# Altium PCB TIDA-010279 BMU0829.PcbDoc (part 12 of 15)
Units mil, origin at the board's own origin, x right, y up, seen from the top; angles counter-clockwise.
Board outline 11269.69 x 4438.98 mil, 4 copper layers (Top Layer, Signal Layer 1, Signal Layer 2, Bottom Layer), stack 61.6 mil thick; 1494 components, 725 nets, 3766 pads, 2728 vias.
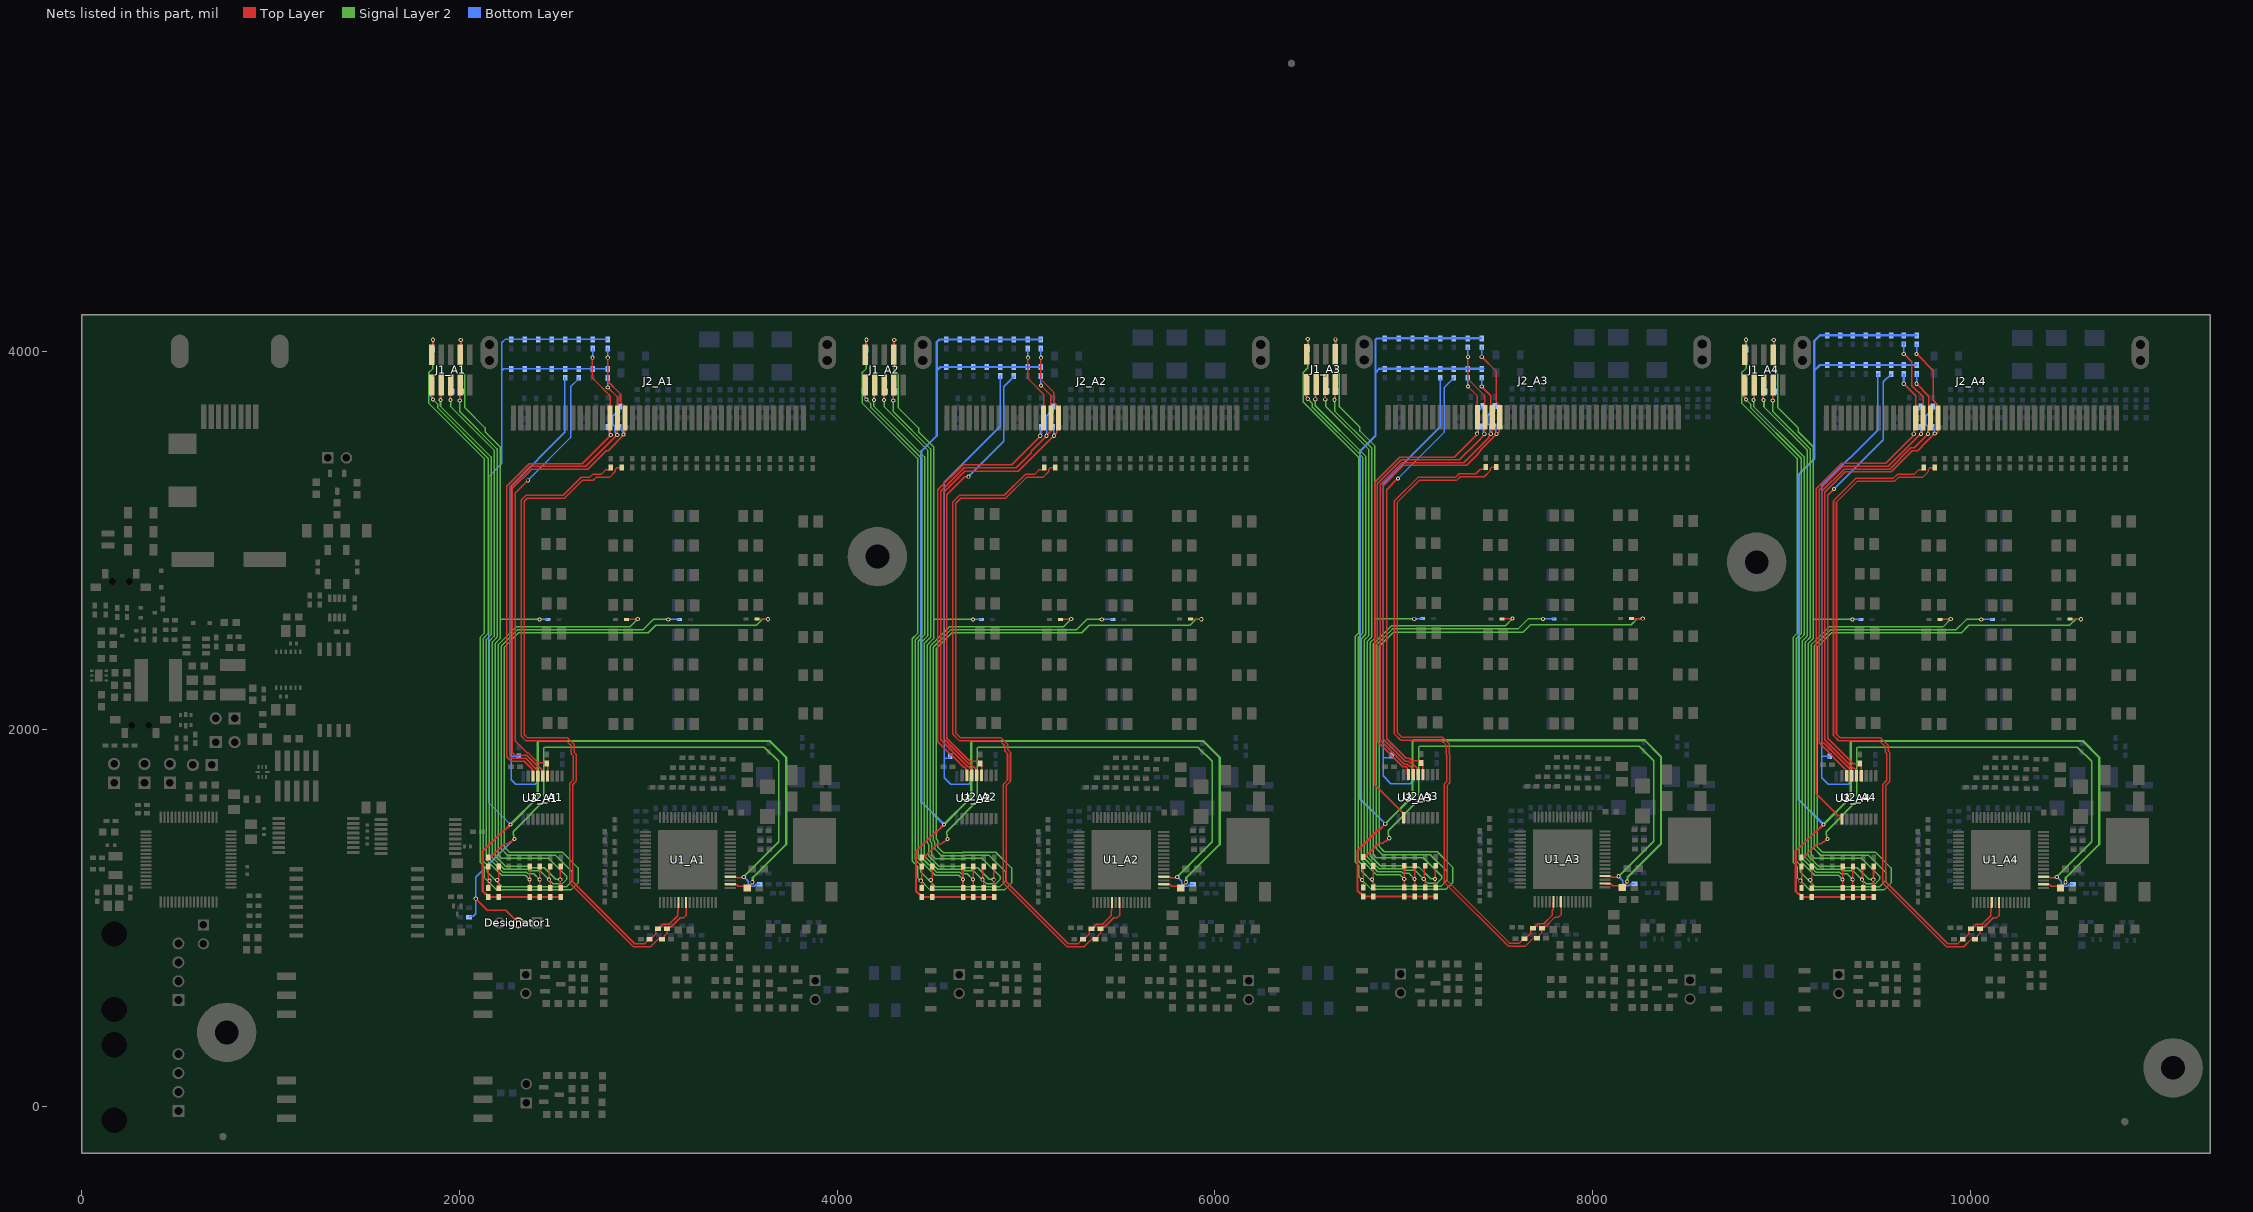
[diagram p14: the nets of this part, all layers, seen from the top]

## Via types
v1: diameter 22.01, hole 12.01, Top Layer to Bottom Layer, tented both sides, 2578 vias
v2: diameter 19.68, hole 7.87, Top Layer to Bottom Layer, tented both sides, 144 vias
v3: diameter 92.52, hole 49.21, Top Layer to Bottom Layer, 4 vias
v4: diameter 19.68, hole 7.87, Top Layer to Bottom Layer, 2 vias

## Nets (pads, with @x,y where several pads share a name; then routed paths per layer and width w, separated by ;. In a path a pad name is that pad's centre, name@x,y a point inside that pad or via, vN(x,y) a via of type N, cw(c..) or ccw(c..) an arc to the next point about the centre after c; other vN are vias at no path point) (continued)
TS11_A3: C122_A3.1 J2_A3.27 R218_A3.1 U2_A3.1 | length 2916.5
  Top Layer w7: U2_A3.1@6998.99,1531 6998.99,1551.67 6845.14,1705.52 6845.14,3296.04 6845.14,3305.88 6979.55,3440.29 7267.9,3440.29 v1@7391.73,3564.12 ; J2_A3.27@7389.59,3650.33 7391.73,3648.19 v1@7391.73,3562.99
  Top Layer w8: v1(7339.1,3813.3) 7389.59,3762.8 7389.59,3702.93 J2_A3.27@7391.73,3700.79
  Bottom Layer w7: v1@7391.73,3564.12 7392.74,3565.13 7392.74,3681.57 7417.43,3706.26 C122_A3.1@7417.43,3710.2
  Bottom Layer w8: R218_A3.1@7338.3,3860.24 7338.3,3819.77 7339.17,3818.9 v1@7342.52,3818.9
  other v1: 7388,3564.12
TS11_A4: C122_A4.1 J2_A4.27 R218_A4.1 U2_A4.1 | length 2896.6
  Top Layer w7: U2_A4.1@9320.14,1524.55 9320.14,1534.91 9314.78,1540.27 9300.53,1540.27 9184.01,1656.79 9184.01,3272.39 9318.34,3406.72 9551.65,3406.72 9697.05,3552.12 9697.05,3560.12 v1(9699.92,3562.99) ; v1(9647.07,3828.74) 9709.82,3765.99 J2_A4.27@9709.82,3705.89 ; v1@9704.72,3571.63 9704.72,3642.02 J2_A4.27@9709.82,3647.12
  Top Layer w12: J2_A4.27@9704.72,3700.79 J2_A4.27@9709.82,3705.89
  Bottom Layer w7: v1(9699.92,3562.99) 9699.92,3653.37 9714.57,3668.02 9714.57,3679.96 9737.66,3703.05 C122_A4.1@9737.66,3706.99
  Bottom Layer w12: R218_A4.1@9645.67,3877.95 9647.07,3876.55 v1(9647.07,3828.74)
TS12_A1: C117_A1.1 J2_A1.7 R217_A1.1 U2_A1.15 | length 2795.7
  Top Layer w7: 2384.68,1788.55 2342.52,1830.71 2273.62,1830.71 2250.37,1853.96 2250.37,3286.22 2369.88,3405.73 2648.8,3405.73 2797.35,3554.29 J2_A1.7@2797.35,3647.12
  Top Layer w8: 2384.68,1788.55 2384.68,1757.35 U2_A1.15@2389.54,1752.49 ; v1(2703.88,3966.54) 2703.88,3858.25 2797.35,3764.78 2797.35,3693.02 J2_A1.7@2795.28,3690.94
  Bottom Layer w7: C117_A1.1@2784.32,3598.72 2792.63,3590.41 2792.63,3569.92 2800.6,3561.94 v1@2800.6,3557.88
  Bottom Layer w8: v1@2706.69,3966.54 2705.29,3967.94 2705.29,4014.34 R217_A1.1@2706.69,4015.75
  other v1: 2800.6,3557.53
TS12_A2: C117_A2.1 J2_A2.7 R217_A2.1 U2_A2.15 | length 2733.2
  Top Layer w7: U2_A2.15@4687.14,1755.85 4681.78,1761.2 4681.78,1788.94 4673.98,1796.75 4669.79,1796.75 4533.53,1933 4533.53,3266.23 4667.02,3399.72 4923.56,3399.72 5075,3551.16 5075,3557.21 5084.02,3566.23 5084.02,3638.77 J2_A2.7@5092.37,3647.12
  Top Layer w8: v1(5009.84,3966.54) 5009.84,3855.44 5092.37,3772.92 5092.37,3704.57 J2_A2.7@5088.58,3700.79
  Bottom Layer w7: v1(5075,3553.15) 5075,3594.39 C117_A2.1@5079.33,3598.72
  Bottom Layer w8: v1(5009.84,3966.54) R217_A2.1@5009.84,4011.81
TS12_A3: C117_A3.1 J2_A3.7 R217_A3.1 U2_A3.15 | length 2780.6
  Top Layer w7: U2_A3.15@7024.58,1759.35 7019.23,1764.71 7019.23,1792.45 7011.42,1800.25 6994.91,1800.25 6860.02,1935.15 6860.02,3289.88 6860.02,3299.72 6985.71,3425.42 7293.53,3425.42 7387.8,3519.69 v1@7428.96,3560.85 ; v1@7429.4,3562.99 J2_A3.7@7429.4,3649.89
  Top Layer w8: v1(7339.1,3970.78) 7339.1,3854.06 7428.96,3764.19 7428.96,3702.93 J2_A3.7@7431.1,3700.79
  Bottom Layer w7: C117_A3.1@7415.93,3601.93 7421.61,3596.24 v1@7421.61,3562.99
  Bottom Layer w8: R217_A3.1@7338.3,4021.65 7338.3,3977.25 7339.17,3976.38 v1@7342.52,3976.38
  other v1: 7426.12,3562.99
TS12_A4: C117_A4.1 J2_A4.7 R217_A4.1 U2_A4.15 | length 2759.5
  Top Layer w7: U2_A4.15@9345.73,1752.89 9340.37,1758.25 9340.37,1785.99 9198.89,1927.47 9198.89,3266.23 9324.5,3391.85 9565.27,3391.85 9737.02,3563.59 9747.45,3574.03 9747.45,3645.38 J2_A4.7@9749.19,3647.12 ; v1(9647.07,3986.22) 9689.69,3943.61 9689.69,3818.44 9749.19,3758.93 J2_A4.7@9749.19,3695.69
  Top Layer w12: J2_A4.7@9749.19,3695.69 J2_A4.7@9753.94,3690.94
  Bottom Layer w7: v1(9647.07,3986.22) R217_A4.1@9647.07,4037.4 ; C117_A4.1@9736.16,3598.72 9737.61,3597.27 v1(9737.61,3562.99)
  Bottom Layer w12: R217_A4.1@9645.67,4045.28 9647.07,4043.87 R217_A4.1@9647.07,4037.4
TS13_A1: C112_A1.1 J2_A1.28 R216_A1.1 U2_A1.14 | length 2767.2
  Top Layer w7: U2_A1.14@2415.13,1752.49 2409.77,1757.85 2409.77,1785.59 2349.78,1845.58 2279.78,1845.58 2265.25,1860.12 2265.25,3280.06 2376.04,3390.86 2669,3390.86 v1(2835.68,3557.53) ; v1@2836.2,3558.06 2835.68,3558.58 2835.68,3646.08 J2_A1.28@2836.72,3647.12
  Top Layer w8: v1(2785.43,3809.06) 2836.72,3757.77 2836.72,3702.86 J2_A1.28@2834.65,3700.79
  Bottom Layer w7: v1@2835.68,3557.88 2835.68,3561.19 2822.13,3574.74 2822.13,3604.3 2811.73,3614.69 2811.73,3656.65 2829.67,3674.59 2842.65,3674.59 2848.51,3680.44 C112_A1.1@2848.51,3706.99
  Bottom Layer w8: v1(2785.43,3809.06) R216_A1.1@2785.43,3858.27
TS13_A2: C112_A2.1 J2_A2.28 R216_A2.1 U2_A2.14 | length 2730.4
  Top Layer w7: U2_A2.14@4712.73,1755.85 4707.37,1761.2 4707.37,1788.94 4696.36,1799.95 4691.81,1799.95 4680.14,1811.62 4679.62,1811.62 4548.41,1942.84 4548.41,3260.07 4673.18,3384.85 4948.12,3384.85 5026.76,3463.48 5026.76,3471.64 v1(5108.27,3553.15) ; v1@5108.27,3554.66 5129.37,3575.76 5129.37,3644.76 J2_A2.28@5131.74,3647.12
  Top Layer w8: v1(5078.74,3818.9) 5131.74,3765.9 5131.74,3704.57 J2_A2.28@5127.95,3700.79
  Bottom Layer w7: v1(5108.27,3553.15) 5108.27,3658.17 5124.68,3674.59 5137.67,3674.59 5143.53,3680.44 C112_A2.1@5143.53,3706.99
  Bottom Layer w8: v1(5078.74,3818.9) R216_A2.1@5078.74,3868.11
TS13_A3: C112_A3.1 J2_A3.28 R216_A3.1 U2_A3.14 | length 2762.2
  Top Layer w7: U2_A3.14@7049.28,1763.85 7044.82,1768.31 7044.82,1792.45 7034.1,1803.16 7029.54,1803.16 7017.58,1815.12 7001.07,1815.12 6874.89,1941.31 6874.89,3237.52 6874.89,3244.35 6874.89,3283.72 6874.89,3293.56 6991.87,3410.54 7317.09,3410.54 7449.21,3542.66 7449.21,3547.87 7460.28,3558.93 v1(7460.28,3562.99) ; v1(7412.21,3813.3) 7459.98,3765.53 7459.98,3711.28 J2_A3.28@7470.47,3700.79 ; v1@7464.11,3563.13 7466.98,3566 7466.98,3573.4 7468.33,3574.76 J2_A3.28@7468.33,3650.33
  Bottom Layer w7: v1@7411.42,3818.9 7412.21,3819.69 7412.21,3859.44 R216_A3.1@7411.42,3860.24 ; v1(7460.28,3562.99) 7461.24,3563.95 7461.24,3575.47 7453.74,3582.97 7453.74,3607.5 7443.34,3617.9 7443.34,3659.86 7461.28,3677.79 7474.27,3677.79 7480.13,3683.65 C112_A3.1@7480.13,3710.2
TS13_A4: C112_A4.1 J2_A4.28 R216_A4.1 U2_A4.14 | length 2729.6
  Top Layer w7: U2_A4.14@9370.08,1761.81 9365.96,1765.93 9365.96,1785.99 9226.16,1925.79 9221.61,1925.79 9213.76,1933.63 9213.76,3260.07 9330.66,3376.97 9571.44,3376.97 9683.75,3489.28 9701.59,3489.28 v1(9775.3,3562.99) 9775.3,3567.05 9779.91,3571.66 9779.91,3638.47 J2_A4.28@9788.56,3647.12 ; v1(9714.57,3828.74) 9780.21,3763.09 9780.21,3704.04 J2_A4.28@9783.46,3700.79
  Bottom Layer w7: v1(9714.57,3828.74) R216_A4.1@9714.57,3879.92 R216_A4.1@9714.57,3887.79 ; v1(9775.3,3562.99) 9773.97,3564.33 9773.97,3604.3 9763.57,3614.69 9763.57,3656.65 9781.51,3674.59 9794.5,3674.59 9800.36,3680.44 C112_A4.1@9800.36,3706.99
TS14_A1: C109_A1.1 J2_A1.8 R224_A1.1 U2_A1.13 | length 2823.4
  Top Layer w7: U2_A1.13@2440.72,1752.49 2440.72,1773.16 2435.36,1778.52 2435.36,1785.59 2415.46,1805.49 2410.9,1805.49 2355.94,1860.46 2293.09,1860.46 2280.12,1873.42 2280.12,3273.9 2382.2,3375.98 2680.21,3375.98 2778.48,3474.25 2787.48,3474.25 v1@2870.76,3557.53 ; v1(2868.24,3560.05) v1@2870.76,3557.53 ; J2_A1.8@2876.09,3647.12 2876.09,3557.53 v1@2870.76,3557.53
  Top Layer w8: v1(2785.43,3966.54) 2785.43,3841.41 2852.59,3774.25 2852.59,3732.05 J2_A1.8@2874.02,3710.63
  Bottom Layer w7: C109_A1.1@2846.81,3598.72 2846.81,3594.78 2867.89,3573.71 2867.89,3560.41 v1(2868.24,3560.05)
  Bottom Layer w8: v1(2785.43,3966.54) R224_A1.1@2785.43,4015.75
TS14_A2: C109_A2.1 J2_A2.8 R224_A2.1 U2_A2.13 | length 2778
  Top Layer w7: U2_A2.13@4738.32,1755.85 4732.96,1761.2 4732.96,1788.94 4707.08,1814.83 4697.97,1814.83 4686.3,1826.5 4685.78,1826.5 4563.28,1949 4563.28,3253.91 4675.51,3366.14 4958.57,3366.14 5145.58,3553.15 v1(5147.64,3553.15) 5147.64,3554.66 5162.09,3569.11 5162.09,3638.11 J2_A2.8@5171.11,3647.12
  Top Layer w8: v1(5078.74,3966.54) 5078.74,3851.25 5147.61,3782.38 5147.61,3730.34 J2_A2.8@5167.32,3710.63
  Bottom Layer w7: C109_A2.1@5141.83,3598.72 5147.64,3592.91 v1(5147.64,3553.15)
  Bottom Layer w8: v1(5078.74,3966.54) R224_A2.1@5078.74,4015.75
TS14_A3: C109_A3.1 J2_A3.8 R224_A3.1 U2_A3.13 | length 2839.7
  Top Layer w7: U2_A3.13@7075.77,1759.35 7070.41,1764.71 7070.41,1792.45 7044.82,1818.04 7035.71,1818.04 7023.74,1830 7007.24,1830 6889.76,1947.47 6889.76,3287.4 6998.03,3395.67 7332.68,3395.67 7394.13,3457.12 7394.13,3461.5 7407.79,3475.16 7407.79,3478.86 7490.16,3561.23 v1(7490.16,3562.99) 7493.03,3565.86 7497.32,3565.86 7506.33,3574.87 7506.33,3648.96 J2_A3.8@7507.7,3650.33
  Top Layer w8: v1(7412.21,3970.78) 7490.16,3892.83 7490.16,3730.31 7509.84,3710.63 7498.59,3710.63 J2_A3.8@7497.92,3711.29
  Bottom Layer w7: C109_A3.1@7478.42,3601.93 7486.73,3593.62 7486.73,3570.48 7490.16,3567.05 v1(7490.16,3562.99)
  Bottom Layer w8: v1@7411.42,3976.38 7411.81,3976.77 7411.81,4021.26 R224_A3.1@7411.42,4021.65
TS14_A4: C109_A4.1 J2_A4.8 R224_A4.1 U2_A4.13 | length 2851.9
  Top Layer w7: U2_A4.13@9396.91,1752.89 9391.55,1758.25 9391.55,1785.99 9383.74,1793.8 9379.19,1793.8 9228.63,1944.35 9228.63,3253.91 9336.82,3362.1 9579.49,3362.1 9691.8,3474.41 9719.86,3474.41 9766.13,3520.67 v1(9810.72,3565.27) ; v1(9714.57,3986.22) 9803.15,3897.64 9803.15,3740.16 9824.82,3718.48 9824.82,3650.23 J2_A4.8@9827.93,3647.12 9827.93,3572.15 9821.64,3565.86 9815.86,3565.86 v1@9812.99,3562.99
  Bottom Layer w7: v1(9714.57,3986.22) R224_A4.1@9714.57,4035.43 ; C109_A4.1@9798.65,3598.72 9806.96,3590.41 9806.96,3573.08 9810.72,3569.33 v1(9810.72,3565.27)
TS15_A1: C138_A1.1 J1_A1.3 R162_A1.1 R165_A1.2 | length 3071.7
  Top Layer w8: v1(1899.64,3742.7) 1899.64,3816.92 J1_A1.3@1903.97,3821.25 ; R162_A1.1@2371.08,1158.67 2370.93,1158.82 2370.93,1203.52 v1(2370.77,1203.67) 2370.93,1203.83 2370.93,1273.21 R165_A1.2@2371.08,1273.36
  Signal Layer 2 w8: v1@1895.89,3742.01 1899.64,3738.26 1899.64,3708.5 2167.57,3440.57 2167.57,2499.11 2161.95,2493.48 2142.81,2474.34 2142.81,1306.61 2161.95,1287.47 2223.66,1225.76 2348.68,1225.76 v1(2370.77,1203.67)
  Bottom Layer w8: v1(1899.64,3742.7) 1901.89,3744.95 1901.89,3786.23 C138_A1.1@1904.13,3788.48
TS15_A2: C138_A2.1 J1_A2.3 R162_A2.1 R165_A2.2 | length 3083
  Top Layer w8: v1(4194.65,3742.7) 4194.65,3816.92 J1_A2.3@4198.99,3821.25 ; R162_A2.1@4666.1,1158.67 4665.94,1158.82 4665.94,1203.52 v1(4665.79,1203.67) 4665.94,1203.83 4665.94,1273.21 R165_A2.2@4666.1,1273.36
  Signal Layer 2 w8: v1(4194.65,3742.7) 4191.59,3742.7 4190.91,3742.01 4194.65,3738.26 4194.65,3708.5 4462.59,3440.57 4462.59,2499.11 4456.96,2493.48 4429.11,2465.63 4429.11,1315.32 4456.96,1287.47 4518.67,1225.76 4643.7,1225.76 v1(4665.79,1203.67)
  Bottom Layer w8: v1(4194.65,3742.7) 4196.9,3744.95 4196.9,3786.23 C138_A2.1@4199.15,3788.48
TS15_A3: C138_A3.1 J1_A3.3 R162_A3.1 R165_A3.2 | length 3071.7
  Top Layer w8: v1(6531.25,3745.9) 6531.25,3820.12 J1_A3.3@6535.58,3824.46 ; R162_A3.1@7002.69,1161.88 7002.54,1162.03 7002.54,1206.73 v1(7002.39,1206.88) 7002.54,1207.03 7002.54,1276.41 R165_A3.2@7002.69,1276.57
  Signal Layer 2 w8: v1@6527.5,3745.22 6531.25,3741.47 6531.25,3711.71 6799.19,3443.78 6799.19,2502.32 6793.56,2496.69 6774.42,2477.55 6774.42,1309.82 6793.56,1290.68 6855.27,1228.97 6980.3,1228.97 v1(7002.39,1206.88)
  Bottom Layer w8: v1(6531.25,3745.9) 6533.5,3748.15 6533.5,3789.44 C138_A3.1@6535.75,3791.69
TS15_A4: C138_A4.1 J1_A4.3 R162_A4.1 R165_A4.2 | length 3071.7
  Top Layer w8: v1(8851.48,3742.7) 8851.48,3816.92 J1_A4.3@8855.81,3821.25 ; R162_A4.1@9322.92,1158.67 9322.77,1158.82 9322.77,1203.52 v1(9322.62,1203.67) 9322.77,1203.83 9322.77,1273.21 R165_A4.2@9322.92,1273.36
  Signal Layer 2 w8: v1@8847.73,3742.01 8851.48,3738.26 8851.48,3708.5 9119.42,3440.57 9119.42,2499.11 9113.79,2493.48 9094.65,2474.34 9094.65,1306.61 9113.79,1287.47 9175.5,1225.76 9300.53,1225.76 v1(9322.62,1203.67)
  Bottom Layer w8: v1(8851.48,3742.7) 8853.73,3744.95 8853.73,3786.23 C138_A4.1@8855.98,3788.48
TS16_A1: C132_A1.1 J1_A1.5 R158_A1.1 R159_A1.2 | length 3088.1
  Top Layer w8: v1(1952.13,3742.7) 1952.13,3819.41 J1_A1.5@1953.97,3821.25 ; R158_A1.1@2426.09,1158.67 2425.25,1159.51 2425.25,1202.83 v1(2424.4,1203.67) 2425.25,1204.51 2425.25,1272.52 R159_A1.2@2426.09,1273.36
  Signal Layer 2 w8: v1@1954.94,3742.01 1954.94,3705.47 2183.45,3476.96 2183.45,2492.54 2158.68,2467.77 2158.68,1313.19 2230.23,1241.64 2355.26,1241.64 2362.67,1234.22 2393.85,1234.22 v1(2424.4,1203.67)
  Bottom Layer w8: v1(1952.13,3742.7) 1952.13,3765.7 1954.16,3767.73 1954.16,3778.68 C132_A1.1@1961.97,3786.49
TS16_A2: C132_A2.1 J1_A2.5 R158_A2.1 R159_A2.2 | length 3098.4
  Top Layer w8: v1(4247.15,3742.7) 4247.15,3819.41 J1_A2.5@4248.99,3821.25 ; R158_A2.1@4721.11,1158.67 4720.26,1159.51 4720.26,1202.83 v1(4719.42,1203.67) 4720.26,1204.51 4720.26,1272.52 R159_A2.2@4721.11,1273.36
  Signal Layer 2 w8: v1(4247.15,3742.7) 4247.83,3742.01 4249.96,3742.01 4249.96,3705.47 4478.46,3476.96 4478.46,2492.54 4444.99,2459.06 4444.99,1321.9 4525.25,1241.64 4650.27,1241.64 4657.69,1234.22 4688.87,1234.22 v1(4719.42,1203.67)
  Bottom Layer w8: v1(4247.15,3742.7) 4247.15,3765.7 4249.17,3767.73 4249.17,3778.68 C132_A2.1@4256.99,3786.49
TS16_A3: C132_A3.1 J1_A3.5 R158_A3.1 R159_A3.2 | length 3088.1
  Top Layer w8: v1(6583.74,3745.9) 6583.74,3822.62 J1_A3.5@6585.58,3824.46 ; R158_A3.1@7057.7,1161.88 7056.86,1162.72 7056.86,1206.04 v1(7056.02,1206.88) 7056.86,1207.72 7056.86,1275.73 R159_A3.2@7057.7,1276.57
  Signal Layer 2 w8: v1@6586.56,3745.22 6586.56,3708.68 6815.06,3480.17 6815.06,2495.75 6790.29,2470.98 6790.29,1316.4 6861.85,1244.84 6986.87,1244.84 6994.29,1237.43 7025.47,1237.43 v1(7056.02,1206.88)
  Bottom Layer w8: v1(6583.74,3745.9) 6583.74,3768.91 6585.77,3770.94 6585.77,3781.89 C132_A3.1@6593.58,3789.7
TS16_A4: C132_A4.1 J1_A4.5 R158_A4.1 R159_A4.2 | length 3088.1
  Top Layer w8: v1(8903.97,3742.7) 8903.97,3819.41 J1_A4.5@8905.81,3821.25 ; R158_A4.1@9377.93,1158.67 9377.09,1159.51 9377.09,1202.83 v1(9376.25,1203.67) 9377.09,1204.52 9377.09,1272.52 R159_A4.2@9377.93,1273.36
  Signal Layer 2 w8: v1@8906.79,3742.01 8906.79,3705.47 9135.29,3476.96 9135.29,2492.54 9110.52,2467.77 9110.52,1313.19 9182.08,1241.64 9307.1,1241.64 9314.52,1234.22 9345.7,1234.22 v1(9376.25,1203.67)
  Bottom Layer w8: v1(8903.97,3742.7) 8903.97,3765.7 8906,3767.73 8906,3778.68 C132_A4.1@8913.81,3786.49
TS17_A1: C128_A1.1 J1_A1.7 R156_A1.1 R157_A1.2 RT1_A1.1 | length 5620.7
  Top Layer w8: v1(2001.59,3740.12) 2001.59,3818.87 J1_A1.7@2003.97,3821.25 ; R156_A1.1@2481.1,1158.67 2481.1,1191.78 2473.78,1199.09 v1(2473.78,1202.88) 2476.46,1205.56 2476.46,1268.72 R157_A1.2@2481.1,1273.36 ; RT1_A1.1@2883.92,2580.3 2885.16,2581.55 2942.5,2581.55 v1(2943.75,2582.8)
  Signal Layer 2 w8: v1(2001.59,3740.12) 2001.59,3681.27 2199.32,3483.54 2199.32,2485.96 2174.55,2461.19 2174.55,1319.76 2236.81,1257.51 2361.83,1257.51 2369.25,1250.1 2426.57,1250.1 2496.66,1180.01 2542.78,1180.01 2568.9,1206.12 2568.9,1218.09 2470.84,1316.15 2223.07,1316.15 2206.3,1332.92 2206.3,2448.04 2301.25,2542.99 2904.77,2542.99 v1@2944.12,2582.34
  Bottom Layer w8: v1(2001.59,3740.12) 2001.59,3763.12 2004.16,3765.69 2004.16,3778.68 C128_A1.1@2011.97,3786.49
TS17_A2: C128_A2.1 J1_A2.7 R156_A2.1 R157_A2.2 RT1_A2.1 | length 5637.9
  Top Layer w8: v1(4296.6,3740.12) 4296.6,3818.87 J1_A2.7@4298.99,3821.25 ; R156_A2.1@4776.11,1158.67 4776.11,1191.78 4768.8,1199.09 v1(4768.8,1202.88) 4771.48,1205.56 4771.48,1268.72 R157_A2.2@4776.11,1273.36 ; RT1_A2.1@5178.93,2580.3 5180.18,2581.55 5237.51,2581.55 v1(5238.76,2582.8)
  Signal Layer 2 w8: v1(4296.6,3740.12) 4296.6,3681.27 4494.34,3483.54 4494.34,2485.96 4460.86,2452.48 4460.86,1328.47 4531.83,1257.51 4656.85,1257.51 4664.26,1250.1 4721.59,1250.1 v1(4768.8,1202.88) 4791.67,1180.01 4837.8,1180.01 4863.91,1206.12 4863.91,1218.09 4765.85,1316.15 4680.8,1316.15 4678.13,1313.48 4520.75,1313.48 4501.32,1332.92 4501.32,1395.83 4492.61,1404.54 4492.61,2439.33 4596.26,2542.99 5199.78,2542.99 5239.14,2582.34 5238.76,2582.72 v1(5238.76,2582.8)
  Bottom Layer w8: v1(4296.6,3740.12) 4296.6,3763.12 4299.17,3765.69 4299.17,3778.68 C128_A2.1@4306.99,3786.49
TS17_A3: C128_A3.1 J1_A3.7 R156_A3.1 R157_A3.2 RT1_A3.1 | length 5620.7
  Top Layer w8: v1(6633.2,3743.32) 6633.2,3822.08 J1_A3.7@6635.58,3824.46 ; R156_A3.1@7112.71,1161.88 7112.71,1194.98 7105.39,1202.3 v1(7105.39,1206.09) 7108.07,1208.77 7108.07,1271.93 R157_A3.2@7112.71,1276.57 ; RT1_A3.1@7515.53,2583.51 7516.77,2584.76 7574.11,2584.76 v1(7575.36,2586)
  Signal Layer 2 w8: v1(6633.2,3743.32) 6633.2,3684.48 6830.94,3486.75 6830.94,2489.17 6806.17,2464.4 6806.17,1322.97 6868.42,1260.72 6993.45,1260.72 7000.86,1253.3 7058.18,1253.3 7128.27,1183.21 7174.39,1183.21 7200.51,1209.33 7200.51,1221.3 7102.45,1319.36 6854.68,1319.36 6837.91,1336.12 6837.91,2451.25 6932.86,2546.2 7536.38,2546.2 v1@7575.73,2585.55
  Bottom Layer w8: v1(6633.2,3743.32) 6633.2,3766.33 6635.77,3768.9 6635.77,3781.89 C128_A3.1@6643.58,3789.7
TS17_A4: C128_A4.1 J1_A4.7 R156_A4.1 R157_A4.2 RT1_A4.1 | length 5620.7
  Top Layer w8: v1(8953.43,3740.12) 8953.43,3818.87 J1_A4.7@8955.81,3821.25 ; R156_A4.1@9432.94,1158.67 9432.94,1191.78 9425.62,1199.09 v1(9425.62,1202.88) 9428.3,1205.56 9428.3,1268.72 R157_A4.2@9432.94,1273.36 ; RT1_A4.1@9835.76,2580.3 9837,2581.55 9894.34,2581.55 v1(9895.59,2582.8)
  Signal Layer 2 w8: v1(8953.43,3740.12) 8953.43,3681.27 9151.17,3483.54 9151.17,2485.96 9126.4,2461.19 9126.4,1319.76 9188.65,1257.51 9313.68,1257.51 9321.09,1250.1 9378.41,1250.1 9448.5,1180.01 9494.62,1180.01 9520.74,1206.12 9520.74,1218.09 9422.68,1316.15 9174.91,1316.15 9158.14,1332.92 9158.14,2448.04 9253.09,2542.99 9856.61,2542.99 v1@9895.96,2582.34
  Bottom Layer w8: v1(8953.43,3740.12) 8953.43,3763.12 8956,3765.69 8956,3778.68 C128_A4.1@8963.81,3786.49
TS18_A1: C123_A1.1 J1_A1.8 R152_A1.1 R153_A1.2 RT2_A1.1 | length 3728.8
  Top Layer w8: J1_A1.8@2003.97,3981.48 2006.83,3984.35 v1(2006.83,4060.32) ; R152_A1.1@2536.11,1158.67 2534.71,1160.07 2534.71,1201.48 v1(2533.31,1202.88) 2534.71,1204.28 2534.71,1271.96 R153_A1.2@2536.11,1273.36
  Signal Layer 2 w8: v1(2006.83,4060.32) 2006.83,3898.37 2027.56,3877.65 2027.56,3702.89 2135.83,3594.62 2135.83,3574.7 2215.2,3495.33 2215.2,2580.43 ; v1(2423.71,2580.36) 2215.26,2580.36 2215.2,2580.43 ; v1(2533.31,1202.88) 2531.6,1204.59 2510.3,1204.59 2448.92,1265.97 2375.82,1265.97 2368.41,1273.38 2243.38,1273.38 2190.43,1326.34 2190.43,1351.79 2190.43,2454.62 2215.2,2479.39 2215.2,2580.43
  Bottom Layer w8: C123_A1.1@2005.4,4006.54 2006.12,4007.25 2006.12,4059.6 v1(2006.83,4060.32) ; v1(2423.71,2580.36) 2424.11,2580.76 2467.29,2580.76 RT2_A1.1@2467.7,2581.17
TS18_A2: C123_A2.1 J1_A2.8 R152_A2.1 R153_A2.2 RT2_A2.1 | length 3736
  Top Layer w8: J1_A2.8@4298.99,3981.48 4301.85,3984.35 v1(4301.85,4060.32) ; R152_A2.1@4831.12,1158.67 4829.72,1160.07 4829.72,1201.48 v1(4828.32,1202.88) 4829.72,1204.28 4829.72,1271.96 R153_A2.2@4831.12,1273.36
  Signal Layer 2 w8: v1(4301.85,4060.32) 4301.85,3898.37 4322.57,3877.65 4322.57,3702.89 4430.84,3594.62 4430.84,3574.7 4510.21,3495.33 4510.21,2580.43 ; v1(4718.72,2580.36) 4510.28,2580.36 4510.21,2580.43 ; v1(4828.32,1202.88) 4826.61,1204.59 4805.32,1204.59 4743.94,1265.97 4670.84,1265.97 4663.43,1273.38 4538.4,1273.38 4485.44,1326.34 4485.44,1389.25 4476.73,1397.96 4476.73,2445.91 4510.21,2479.39 4510.21,2580.43
  Bottom Layer w8: C123_A2.1@4300.42,4006.54 4301.13,4007.25 4301.13,4059.6 v1(4301.85,4060.32) ; v1(4718.72,2580.36) 4719.13,2580.76 4762.31,2580.76 RT2_A2.1@4762.71,2581.17
TS18_A3: C123_A3.1 J1_A3.8 R152_A3.1 R153_A3.2 RT2_A3.1 | length 3728.8
  Top Layer w8: J1_A3.8@6635.58,3984.69 6638.45,3987.56 v1(6638.45,4063.53) ; R152_A3.1@7167.72,1161.88 7166.32,1163.28 7166.32,1204.69 v1(7164.92,1206.09) 7166.32,1207.49 7166.32,1275.17 R153_A3.2@7167.72,1276.57
  Signal Layer 2 w8: v1(6638.45,4063.53) 6638.45,3901.58 6659.17,3880.85 6659.17,3706.09 6767.44,3597.83 6767.44,3577.91 6846.81,3498.54 6846.81,2583.64 ; v1(7055.32,2583.57) 6846.88,2583.57 6846.81,2583.64 ; v1(7164.92,1206.09) 7163.21,1207.8 7141.91,1207.8 7080.54,1269.18 7007.44,1269.18 7000.02,1276.59 6875,1276.59 6822.04,1329.55 6822.04,1355 6822.04,2457.83 6846.81,2482.59 6846.81,2583.64
  Bottom Layer w8: C123_A3.1@6637.01,4009.75 6637.73,4010.46 6637.73,4062.81 v1(6638.45,4063.53) ; v1(7055.32,2583.57) 7055.72,2583.97 7098.91,2583.97 RT2_A3.1@7099.31,2584.37
TS18_A4: C123_A4.1 J1_A4.8 R152_A4.1 R153_A4.2 RT2_A4.1 | length 3728.8
  Top Layer w8: J1_A4.8@8955.81,3981.48 8958.68,3984.35 v1(8958.68,4060.32) ; R152_A4.1@9487.95,1158.67 9486.55,1160.07 9486.55,1201.48 v1(9485.15,1202.88) 9486.55,1204.28 9486.55,1271.96 R153_A4.2@9487.95,1273.36
  Signal Layer 2 w8: v1(8958.68,4060.32) 8958.68,3898.37 8979.4,3877.65 8979.4,3702.89 9087.67,3594.62 9087.67,3574.7 9167.04,3495.33 9167.04,2580.43 ; v1@9375.55,2580.36 9167.11,2580.36 9167.04,2580.43 ; v1(9485.15,1202.88) 9483.44,1204.59 9462.14,1204.59 9400.77,1265.97 9327.67,1265.97 9320.25,1273.38 9195.23,1273.38 9142.27,1326.34 9142.27,1351.79 9142.27,2454.62 9167.04,2479.39 9167.04,2580.43
  Bottom Layer w8: C123_A4.1@8957.24,4006.54 8957.96,4007.25 8957.96,4059.6 v1(8958.68,4060.32) ; v1(9375.55,2580.36) 9375.95,2580.76 9419.14,2580.76 RT2_A4.1@9419.54,2581.17
TS19_A1: C118_A1.1 J1_A1.1 R147_A1.1 R150_A1.2 RT3_A1.1 | length 5942.1
  Top Layer w8: J1_A1.1@1853.97,3821.25 1853.97,3754.7 1859.3,3749.37 v1(1859.3,3745.58) ; v1@2197.93,1202.32 2207.17,1211.55 R150_A1.2@2207.17,1272.04 ; v1(2199.83,1200.42) 2199.83,1196.63 2206.77,1189.69 2206.77,1157.75 R147_A1.1@2207.17,1157.35 ; v1(3105.17,2580.36) v1@3105.51,2580.7
  Signal Layer 2 w8: v1(1859.3,3745.58) 1883.76,3721.11 1883.76,3701.93 2151.7,3433.99 2151.7,2505.69 2126.93,2480.92 2126.93,1300.04 2146.07,1280.9 2146.07,1244.27 v1@2194.88,1195.47 ; v1(2199.83,1200.42) v1@2194.88,1195.47 ; v1(3105.17,2580.36) 3086.57,2580.36 3086.51,2580.3 3026.4,2580.3 2973.21,2527.11 2307.82,2527.11 2222.18,2441.47 2222.18,1364.94 2255.09,1332.03 2508.57,1332.03 2598.43,1242.17 2598.43,1197.66 2564.9,1164.13 2226.21,1164.13 v1@2194.88,1195.47
  Bottom Layer w8: C118_A1.1@1845.97,3788.75 1847.67,3787.05 1847.67,3761 1859.3,3749.37 v1(1859.3,3745.58) ; v1@3105.2,2580.33 3164.19,2580.33 RT3_A1.1@3164.62,2580.76
TS19_A2: C118_A2.1 J1_A2.1 R147_A2.1 R150_A2.2 RT3_A2.1 | length 5958.7
  Top Layer w8: J1_A2.1@4148.99,3821.25 4148.99,3754.7 4154.32,3749.37 v1(4154.32,3745.58) ; v1@4492.95,1202.32 4502.19,1211.55 R150_A2.2@4502.19,1272.04 ; v1(4494.84,1200.42) 4494.84,1196.63 4501.79,1189.69 4501.79,1157.75 R147_A2.1@4502.19,1157.35 ; v1(5400.19,2580.36) v1@5400.53,2580.7
  Signal Layer 2 w8: v1(4154.32,3745.58) 4178.78,3721.11 4178.78,3701.93 4446.72,3433.99 4446.72,2505.69 4413.24,2472.21 4413.24,1308.75 4441.09,1280.9 4441.09,1244.27 v1@4489.89,1195.47 ; v1(4494.84,1200.42) v1@4489.89,1195.47 ; v1(5400.19,2580.36) 5381.58,2580.36 5381.52,2580.3 5321.41,2580.3 5268.22,2527.11 4602.84,2527.11 4508.48,2432.76 4508.48,1411.11 4517.19,1402.4 4517.19,1364.94 4552.78,1329.36 4671.55,1329.36 4674.22,1332.03 4803.59,1332.03 4893.44,1242.17 4893.44,1197.66 4859.91,1164.13 4521.23,1164.13 v1@4489.89,1195.47
  Bottom Layer w8: C118_A2.1@4140.99,3788.75 4142.69,3787.05 4142.69,3761 4154.32,3749.37 v1(4154.32,3745.58) ; v1@5400.22,2580.33 5459.2,2580.33 RT3_A2.1@5459.63,2580.76
TS19_A3: C118_A3.1 J1_A3.1 R147_A3.1 R150_A3.2 RT3_A3.1 | length 5942.1
  Top Layer w8: J1_A3.1@6485.58,3824.46 6485.58,3757.91 6490.91,3752.57 v1(6490.91,3748.78) ; v1@6829.55,1205.53 6838.78,1214.76 R150_A3.2@6838.78,1275.25 ; v1(6831.44,1203.63) 6831.44,1199.84 6838.38,1192.9 6838.38,1160.96 R147_A3.1@6838.78,1160.56 ; v1(7736.79,2583.57) v1@7737.12,2583.9
  Signal Layer 2 w8: v1(6490.91,3748.78) 6515.38,3724.32 6515.38,3705.14 6783.31,3437.2 6783.31,2508.9 6758.54,2484.13 6758.54,1303.25 6777.69,1284.11 6777.69,1247.48 v1@6826.49,1198.68 ; v1(6831.44,1203.63) v1@6826.49,1198.68 ; v1(7736.79,2583.57) 7718.18,2583.57 7718.12,2583.51 7658.01,2583.51 7604.82,2530.32 6939.43,2530.32 6853.79,2444.68 6853.79,1368.15 6886.7,1335.23 7140.18,1335.23 7230.04,1245.38 7230.04,1200.87 7196.51,1167.34 6857.83,1167.34 v1@6826.49,1198.68
  Bottom Layer w8: C118_A3.1@6477.58,3791.95 6479.28,3790.26 6479.28,3764.21 6490.91,3752.57 v1(6490.91,3748.78) ; v1@7736.82,2583.54 7795.8,2583.54 RT3_A3.1@7796.23,2583.97
TS19_A4: C118_A4.1 J1_A4.1 R147_A4.1 R150_A4.2 RT3_A4.1 | length 5942.1
  Top Layer w8: J1_A4.1@8805.81,3821.25 8805.81,3754.7 8811.14,3749.37 v1(8811.14,3745.58) ; v1@9149.78,1202.32 9159.01,1211.55 R150_A4.2@9159.01,1272.04 ; v1(9151.67,1200.42) 9151.67,1196.63 9158.61,1189.69 9158.61,1157.75 R147_A4.1@9159.01,1157.35 ; v1(10057.02,2580.36) v1@10057.35,2580.7
  Signal Layer 2 w8: v1(8811.14,3745.58) 8835.61,3721.11 8835.61,3701.93 9103.54,3433.99 9103.54,2505.69 9078.77,2480.92 9078.77,1300.04 9097.92,1280.9 9097.92,1244.27 v1@9146.72,1195.47 ; v1(9151.67,1200.42) v1@9146.72,1195.47 ; v1(10057.02,2580.36) 10038.41,2580.36 10038.35,2580.3 9978.24,2580.3 9925.05,2527.11 9259.66,2527.11 9174.02,2441.47 9174.02,1364.94 9206.93,1332.03 9460.41,1332.03 9550.27,1242.17 9550.27,1197.66 9516.74,1164.13 9178.06,1164.13 v1@9146.72,1195.47
  Bottom Layer w8: C118_A4.1@8797.81,3788.75 8799.51,3787.05 8799.51,3761 8811.14,3749.37 v1(8811.14,3745.58) ; v1@10057.05,2580.33 10116.03,2580.33 RT3_A4.1@10116.46,2580.76
TS20_A1: C113_A1.1 J1_A1.2 R144_A1.1 R145_A1.2 RT4_A1.1 | length 6888.5
  Top Layer w8: J1_A1.2@1857.95,3972.62 1859.6,3974.27 v1@1859.6,4055.89 ; R144_A1.1@2153.54,1157.48 v1@2153.54,1197.66 ; R145_A1.2@2153.54,1272.18 v1@2153.54,1197.66 ; v1(2158.7,1197.66) v1@2153.54,1197.66 ; RT4_A1.1@3574.56,2582.39 3574.98,2581.97 3632.52,2581.97 v1(3632.94,2581.55)
  Signal Layer 2 w8: v1(1859.8,4061.75) 1859.8,3909.43 1836.42,3886.06 1836.42,3726.82 2130.2,3433.05 2130.2,2506.63 2111.06,2487.49 2111.06,1293.46 2130.2,1274.32 2130.2,1214.99 2147.53,1197.66 v1@2153.12,1192.07 ; v1(2158.7,1197.66) v1@2153.12,1192.07 ; v1@3632.52,2581.97 3605.05,2581.97 3572.3,2549.21 3039.3,2549.21 2999.93,2509.84 2313,2509.84 2238.05,2434.89 2238.05,1374.76 2264.91,1347.9 2544.8,1347.9 2627.95,1264.74 2627.95,1185.73 2590.48,1148.26 2196.93,1148.26 v1@2153.12,1192.07
  Bottom Layer w8: C113_A1.1@1859.8,4009.21 v1(1859.8,4061.75) ; v1@3632.52,2581.97 v1(3632.94,2581.55)
TS20_A2: C113_A2.1 J1_A2.2 R144_A2.1 R145_A2.2 RT4_A2.1 | length 6898.6
  Top Layer w8: J1_A2.2@4152.96,3972.62 4154.61,3974.27 v1@4154.61,4055.89 ; v1(4442.54,1197.66) v1@4448.56,1197.66 ; R144_A2.1@4448.56,1157.48 v1@4448.56,1197.66 ; R145_A2.2@4448.56,1272.18 v1@4448.56,1197.66 ; RT4_A2.1@5869.58,2582.39 5870,2581.97 5927.53,2581.97 v1(5927.95,2581.55)
  Signal Layer 2 w8: v1(4154.81,4061.75) 4154.81,3909.43 4131.44,3886.06 4131.44,3726.82 4425.21,3433.05 4425.21,2506.63 4397.36,2478.78 4397.36,1302.17 4425.21,1274.32 4425.21,1214.99 v1(4442.54,1197.66) 4491.95,1148.26 4885.5,1148.26 4922.97,1185.73 4922.97,1264.74 4839.81,1347.9 4667.65,1347.9 4664.98,1345.23 4562.59,1345.23 4533.07,1374.76 4533.07,1408.98 4524.36,1417.69 4524.36,2426.18 4608.02,2509.84 5294.94,2509.84 5334.31,2549.21 5867.31,2549.21 5900.07,2581.97 5927.53,2581.97 v1(5927.95,2581.55)
  Bottom Layer w8: C113_A2.1@4154.81,4009.21 v1(4154.81,4061.75) ; v1@5927.53,2581.97 v1(5927.95,2581.55)
TS20_A3: C113_A3.1 J1_A3.2 R144_A3.1 R145_A3.2 RT4_A3.1 | length 6881.4
  Top Layer w8: J1_A3.2@6489.56,3975.83 6491.21,3977.48 v1@6491.21,4059.1 ; v1(6779.14,1200.87) v1@6785.15,1200.87 ; R144_A3.1@6785.15,1160.69 v1@6785.15,1200.87 ; R145_A3.2@6785.15,1275.38 v1@6785.15,1200.87 ; RT4_A3.1@8206.18,2585.59 8206.59,2585.18 8264.13,2585.18 v1(8264.55,2584.76)
  Signal Layer 2 w8: v1(6491.41,4064.96) 6491.41,3912.64 6468.04,3889.27 6468.04,3730.03 6761.81,3436.25 6761.81,2509.84 6742.67,2490.7 6742.67,1296.67 6761.81,1277.53 6761.81,1218.2 v1(6779.14,1200.87) 6828.54,1151.47 7222.09,1151.47 7259.57,1188.94 7259.57,1267.95 7176.41,1351.11 6896.52,1351.11 6869.66,1377.96 6869.66,2438.1 6944.61,2513.05 7631.54,2513.05 7670.91,2552.42 8203.91,2552.42 8236.66,2585.18 v1@8264.13,2585.18
  Bottom Layer w8: C113_A3.1@6491.41,4012.42 v1(6491.41,4064.96) ; v1@8264.13,2585.18 v1(8264.55,2584.76)
TS20_A4: C113_A4.1 J1_A4.2 R144_A4.1 R145_A4.2 RT4_A4.1 | length 6881.4
  Top Layer w8: J1_A4.2@8809.79,3972.62 8811.44,3974.27 v1@8811.44,4055.89 ; v1(9099.37,1197.66) v1@9105.38,1197.66 ; R144_A4.1@9105.38,1157.49 v1@9105.38,1197.66 ; R145_A4.2@9105.38,1272.18 v1@9105.38,1197.66 ; RT4_A4.1@10526.41,2582.39 10526.82,2581.97 10584.36,2581.97 v1(10584.78,2581.55)
  Signal Layer 2 w8: v1(8811.64,4061.75) 8811.64,3909.43 8788.27,3886.06 8788.27,3726.82 9082.04,3433.05 9082.04,2506.63 9062.9,2487.49 9062.9,1293.46 9082.04,1274.32 9082.04,1214.99 v1(9099.37,1197.66) 9148.77,1148.26 9542.32,1148.26 9579.8,1185.73 9579.8,1264.74 9496.64,1347.9 9216.75,1347.9 9189.89,1374.76 9189.89,2434.89 9264.84,2509.84 9951.77,2509.84 9991.14,2549.21 10524.14,2549.21 10556.89,2581.97 v1@10584.36,2581.97
  Bottom Layer w8: C113_A4.1@8811.64,4009.21 v1(8811.64,4061.75) ; v1@10584.36,2581.97 v1(10584.78,2581.55)
TS_R1_A1: R148_A1.2 R222_A1.1 U3_A1.12 | length 2471
  Bottom Layer w7: R148_A1.2@2312.99,1856.3 2273.62,1856.3 ; U3_A1.12@2415.13,1748.54 2409.77,1743.19 2409.77,1715.45 2401.97,1707.64 2298.26,1707.64 2273.62,1732.28 2273.62,1833.42 2273.62,1856.3 ; R222_A1.1@2560.46,3860.24 2558.49,3858.27 2558.49,3570.61 2273.62,3285.74 2273.62,1856.3
TS_R1_A2: R148_A2.2 R222_A2.1 U3_A2.12 | length 2499.3
  Bottom Layer w7: R148_A2.2@4595.72,1851.13 4589.85,1845.27 4571.03,1845.27 4566.93,1841.17 4566.93,1840.55 4566.93,1742.13 4601.41,1707.64 4696.98,1707.64 4704.79,1715.45 4704.79,1743.19 U3_A2.12@4710.14,1748.54
  Bottom Layer w8: 4566.93,1841.17 4566.93,3307.09 4863.61,3603.77 R222_A2.1@4863.61,3870.08 ; R148_A2.2@4596.46,1850.39 R148_A2.2@4596.46,1858.53 ; R148_A2.2@4598.17,1856.3 4605.98,1864.11 R148_A2.2@4605.98,1869.76
TS_R1_A3: R148_A3.2 R222_A3.1 U3_A3.12 | length 2492.7
  Bottom Layer w7: R148_A3.2@6934.76,1859.51 6934.76,1856.79 6926.45,1848.48 6893.86,1848.48 6889.76,1844.38 ; U3_A3.12@7046.74,1751.75 7041.38,1746.39 7041.38,1718.65 7033.58,1710.85 6930.88,1710.85 6889.76,1751.97 6889.76,1840.55 6889.76,1844.38 ; R222_A3.1@7194.04,3858.27 7194.04,3600.95 7018.29,3425.2 7017.72,3425.2 6889.76,3297.24 6889.76,1844.38
TS_R1_A4: R148_A4.2 R222_A4.1 U3_A4.12 | length 2520.6
  Bottom Layer w7: R148_A4.2@9246.68,1845.27 9254.99,1853.58 R148_A4.2@9254.99,1856.3 9212.6,1856.3 ; U3_A4.12@9366.97,1748.54 9361.61,1743.19 9361.61,1715.45 9353.81,1707.64 9247.08,1707.64 9212.6,1742.13 9212.6,1856.3 ; R222_A4.1@9507.87,3875.7 9507.87,3582.68 9212.6,3287.4 9212.6,1856.3
  Bottom Layer w12: R222_A4.1@9507.87,3875.7 R222_A4.1@9512.09,3879.92
TS_R2_A1: R151_A1.2 R223_A1.1 U2_A1.12 | length 2333.3
  Top Layer w7: R151_A1.2@2461.06,1817.45 2466.31,1812.21 U2_A1.12@2466.31,1752.49
  Top Layer w8: v1(2362.2,3316.93) 2295.5,3250.22 2295.5,1936.79 2356.45,1875.83 2362.31,1875.83 2417.27,1820.87 R151_A1.2@2450.79,1820.87
  Bottom Layer w8: v1(2362.2,3316.93) 2588.58,3543.31 2588.58,3812.71 2632.17,3856.3 R223_A1.1@2632.17,3860.24
TS_R2_A2: R151_A2.2 R223_A2.1 U2_A2.12 | length 2370.2
  Top Layer w7: v1(4694.88,3336.61) 4675.2,3336.61 4580.6,3242.02 4580.6,1952.71 4691.94,1841.37 4692.46,1841.37 4704.13,1829.7 4747.77,1829.7 4753.94,1823.53 R151_A2.2@4753.94,1820.87 ; R151_A2.2@4756.08,1817.45 4763.91,1809.62 U2_A2.12@4763.91,1755.85
  Bottom Layer w7: v1(4694.88,3336.61) 4881.89,3523.62 4881.89,3812.71 4935.32,3866.14 R223_A2.1@4935.32,3870.08
TS_R2_A3: R151_A3.2 R223_A3.1 U2_A3.12 | length 2347.3
  Top Layer w7: v1(6968.5,3326.77) 6909.45,3267.72 6909.45,1948.82 7013.4,1844.87 7029.9,1844.87 7041.87,1832.91 7084.36,1832.91 R151_A3.2@7084.86,1832.41 ; R151_A3.2@7092.67,1820.66 7100.99,1812.35 7100.99,1759.72 U2_A3.12@7101.36,1759.35
  Bottom Layer w8: v1(6968.5,3326.77) 7214.57,3572.83 7214.57,3809.62 R223_A3.1@7265.19,3860.24
TS_R2_A4: R151_A4.2 R223_A4.1 U2_A4.12 | length 2360.7
  Top Layer w7: v1(9277.79,3271.42) 9243.51,3237.14 9243.51,1952.15 9378.2,1817.45 R151_A4.2@9412.9,1817.45 9421.22,1809.14 9421.22,1754.18 U2_A4.12@9422.5,1752.89
  Bottom Layer w7: v1(9277.79,3271.42) 9537.4,3531.03 9537.4,3837.74 R223_A4.1@9579.58,3879.92
TSREF_A1: C46_A1.2 R144_A1.2 R147_A1.2 R152_A1.2 R156_A1.2 R158_A1.2 R162_A1.2 R208_A1.2 R209_A1.2 R210_A1.2 R211_A1.2 R212_A1.2 R213_A1.2 R214_A1.2 R216_A1.2 R217_A1.2 R218_A1.2 R219_A1.2 R220_A1.2 R221_A1.2 R222_A1.2 R223_A1.2 R224_A1.2 U1_A1.50 | length 7311.8
  Top Layer w7: U1_A1.50@3433.88,1179 3436.28,1176.6 3466.97,1176.6 3475.04,1168.54 3514.26,1168.54 C46_A1.2@3524.71,1158.09 ; C46_A1.2@3525.69,1158.09 v1@3547.88,1180.28
  Top Layer w12: v1(2269.82,1495.14) 2231.73,1457.05 2226.67,1457.05 2122.65,1353.03 2122.65,1141.2 2135.98,1127.86 2139.85,1127.86 2153.54,1114.18 R144_A1.2@2153.54,1110.24 2154.13,1110.83 2535.51,1110.83 R152_A1.2@2536.11,1111.43
  Signal Layer 2 w12: v1(2269.82,1495.14) 2414.08,1639.4 2414.08,1930.16 2421.11,1937.19 3643.28,1937.19 3730.31,1850.15 3730.31,1390.17 3552.67,1212.52 3552.67,1191.2 v1(3550.76,1189.29)
  Bottom Layer w8: v1(2269.82,1495.14) 2154.13,1610.83 2154.13,3335.23 2224.41,3405.51 2224.41,3897.64 ; R218_A1.2@2703.88,3907.48 R223_A1.2@2632.17,3907.48 R222_A1.2@2560.46,3907.48 R208_A1.2@2488.75,3907.48 R210_A1.2@2417.04,3907.48 R212_A1.2@2345.33,3907.48 R214_A1.2@2273.62,3907.48 2234.25,3907.48 2224.41,3897.64 ; R218_A1.2@2706.69,3907.48 R216_A1.2@2775.59,3907.48 ; R224_A1.2@2785.43,4064.96 2706.69,4064.96 2632.17,4064.96 2560.46,4064.96 2488.75,4064.96 2417.04,4064.96 2345.33,4064.96 2273.62,4064.96 2244.09,4064.96 2224.41,4045.28 2224.41,3897.64
TSREF_A2: C46_A2.2 R144_A2.2 R147_A2.2 R152_A2.2 R156_A2.2 R158_A2.2 R162_A2.2 R208_A2.2 R209_A2.2 R210_A2.2 R211_A2.2 R212_A2.2 R213_A2.2 R214_A2.2 R216_A2.2 R217_A2.2 R218_A2.2 R219_A2.2 R220_A2.2 R221_A2.2 R222_A2.2 R223_A2.2 R224_A2.2 U1_A2.50 | length 7328.2
  Top Layer w7: U1_A2.50@5728.89,1179 5731.3,1176.6 5761.99,1176.6 5770.05,1168.54 5809.28,1168.54 C46_A2.2@5819.72,1158.09 ; C46_A2.2@5820.71,1158.09 5842.9,1180.28 5842.9,1186.41 v1(5845.77,1189.29)
  Top Layer w12: v1(4564.84,1495.14) 4526.74,1457.05 4521.68,1457.05 4417.67,1353.03 4417.67,1141.2 4431,1127.86 4434.87,1127.86 4448.56,1114.18 R144_A2.2@4448.56,1110.24 4449.15,1110.83 4830.53,1110.83 R152_A2.2@4831.12,1111.43
  Signal Layer 2 w12: v1(4564.84,1495.14) 4709.1,1639.4 4709.1,1930.16 4716.12,1937.19 5938.3,1937.19 6025.33,1850.15 6025.33,1390.17 5847.69,1212.52 5847.69,1191.2 v1(5845.77,1189.29)
  Bottom Layer w12: v1(4564.84,1495.14) 4444.94,1615.04 4444.94,3470.53 4527.56,3553.15 4527.56,3897.64 ; R216_A2.2@5078.74,3917.32 R218_A2.2@5009.84,3917.32 R223_A2.2@4935.32,3917.32 R222_A2.2@4863.61,3917.32 R208_A2.2@4791.9,3917.32 R210_A2.2@4720.19,3917.32 R212_A2.2@4648.48,3917.32 R214_A2.2@4576.77,3917.32 4547.24,3917.32 4527.56,3897.64 ; R224_A2.2@5078.74,4064.96 5076.77,4062.99 R217_A2.2@5009.84,4062.99 R219_A2.2@4935.32,4062.99 R220_A2.2@4863.61,4062.99 R221_A2.2@4791.9,4062.99 R209_A2.2@4720.19,4062.99 R211_A2.2@4648.48,4062.99 4541.34,4062.99 4527.56,4049.21 4527.56,3897.64
TSREF_A3: C46_A3.2 R144_A3.2 R147_A3.2 R152_A3.2 R156_A3.2 R158_A3.2 R162_A3.2 R208_A3.2 R209_A3.2 R210_A3.2 R211_A3.2 R212_A3.2 R213_A3.2 R214_A3.2 R216_A3.2 R217_A3.2 R218_A3.2 R219_A3.2 R220_A3.2 R221_A3.2 R222_A3.2 R223_A3.2 R224_A3.2 U1_A3.50 | length 7364.1
  Top Layer w7: U1_A3.50@8065.49,1182.21 8067.9,1179.81 8098.59,1179.81 8106.65,1171.74 8145.87,1171.74 C46_A3.2@8156.32,1161.3 ; C46_A3.2@8157.3,1161.3 8179.5,1183.49 8179.5,1189.62 v1(8182.37,1192.49)
  Top Layer w12: v1(6901.44,1498.35) 6863.34,1460.25 6858.28,1460.25 6754.26,1356.24 6754.26,1144.4 6767.59,1131.07 6771.47,1131.07 6785.15,1117.39 R144_A3.2@6785.15,1113.45 6785.74,1114.04 7167.13,1114.04 R152_A3.2@7167.72,1114.63
  Signal Layer 2 w12: v1(6901.44,1498.35) 7045.69,1642.61 7045.69,1933.37 7052.72,1940.4 8274.89,1940.4 8361.93,1853.36 8361.93,1393.38 8184.28,1215.73 8184.28,1194.41 v1(8182.37,1192.49)
  Bottom Layer w12: R213_A3.2@6899.61,4068.08 6857.42,4068.08 6850.39,4061.05 6850.39,3887.8 ; R213_A3.2@6899.61,4068.9 R211_A3.2@6972.72,4068.9 R209_A3.2@7045.84,4068.9 R221_A3.2@7118.95,4068.9 R220_A3.2@7192.07,4068.9 R219_A3.2@7265.19,4068.9 R217_A3.2@7338.3,4068.9 R224_A3.2@7407.48,4068.9 ; v1(6901.44,1498.35) 6768.27,1631.51 6768.27,3471.03 6850.39,3553.15 6850.39,3887.8 ; R216_A3.2@7421.26,3907.48 R216_A3.2@7411.42,3907.48 R218_A3.2@7338.3,3907.48 R223_A3.2@7265.19,3907.48 R222_A3.2@7192.07,3907.48 R208_A3.2@7118.95,3907.48 R210_A3.2@7045.84,3907.48 R212_A3.2@6972.72,3907.48 6870.08,3907.48 6850.39,3887.8
TSREF_A4: C46_A4.2 R144_A4.2 R147_A4.2 R152_A4.2 R156_A4.2 R158_A4.2 R162_A4.2 R208_A4.2 R209_A4.2 R210_A4.2 R211_A4.2 R212_A4.2 R213_A4.2 R214_A4.2 R216_A4.2 R217_A4.2 R218_A4.2 R219_A4.2 R220_A4.2 R221_A4.2 R222_A4.2 R223_A4.2 R224_A4.2 U1_A4.50 | length 7328.4
  Top Layer w7: U1_A4.50@10385.72,1179 10388.12,1176.6 10418.82,1176.6 10426.88,1168.54 10466.1,1168.54 C46_A4.2@10476.55,1158.09 ; C46_A4.2@10477.53,1158.09 10499.73,1180.28 10499.73,1186.41 v1(10502.6,1189.29)
  Top Layer w12: v1(9221.67,1495.14) 9183.57,1457.05 9178.51,1457.05 9074.49,1353.03 9074.49,1141.2 9087.82,1127.86 9091.7,1127.86 9105.38,1114.18 R144_A4.2@9105.38,1110.24 9105.97,1110.83 9487.36,1110.83 R152_A4.2@9487.95,1111.43
  Signal Layer 2 w12: v1(9221.67,1495.14) 9365.92,1639.4 9365.92,1930.16 9372.95,1937.19 10595.12,1937.19 10682.16,1850.16 10682.16,1390.17 10504.51,1212.52 10504.51,1191.2 v1(10502.6,1189.29)
  Bottom Layer w12: v1(9221.67,1495.14) 9091.11,1625.7 9091.11,3347.96 9173.23,3430.08 9173.23,3897.64 ; R213_A4.2@9242.13,4084.65 9202.69,4084.58 9173.23,4055.12 9173.23,3897.64 ; R213_A4.2@9242.13,4084.65 R211_A4.2@9309.62,4084.65 R209_A4.2@9377.11,4084.65 R221_A4.2@9444.6,4084.65 R220_A4.2@9510.69,4084.65 R217_A4.2@9647.07,4084.65 R224_A4.2@9714.57,4084.65 ; R216_A4.2@9714.57,3927.17 R218_A4.2@9647.07,3927.17 R223_A4.2@9579.58,3927.17 R222_A4.2@9512.09,3927.17 R208_A4.2@9444.6,3927.17 R210_A4.2@9377.11,3927.17 R212_A4.2@9309.62,3927.17 9202.76,3927.17 9173.23,3897.64
TX/GPIO1_A1: C110_A1.1 Designator1.2 R145_A1.1 R209.1 U1_A1.52 | length 3709.6
  Top Layer w7: v1(2086.61,1102.36) 2147.05,1041.93 2243.9,1041.93 2294.41,991.41 2300.47,991.41 Designator1.2@2303.15,994.09 ; R145_A1.1@2153.54,1319.42 2158.51,1314.45 2236.69,1392.63 2257.41,1392.63 2262.36,1397.59 2263.22,1397.59 2269.02,1403.39 2273.97,1403.39 2289.04,1418.46 v1(2290.81,1418.46) ; U1_A1.52@3463.22,1218.37 U1_A1.52@3433.88,1218.37 3436.28,1215.97 3468.86,1215.97 3471.31,1213.51 3497.43,1213.51 3501.2,1217.28 v1(3505.26,1217.28)
  Signal Layer 2 w7: v1(2290.81,1418.46) 2287.94,1421.33 2287.94,1436.69 2284.74,1439.89 2284.74,1457.38 2376.7,1549.34 2376.7,1552.3 2446.33,1621.92 2446.33,1900.84 2450.43,1904.94 3614.56,1904.94 3690.89,1828.6 3690.89,1402.92 v1(3505.26,1217.28)
  Bottom Layer w7: R209.1@2051.18,1003.94 2057.51,1010.27 2073.26,1010.27 2086.61,1023.62 v1(2086.61,1102.36) 2086.61,1214.26 v1(2290.81,1418.46) ; v1(3505.26,1217.28) 3528.38,1194.16 3528.38,1180.02 3541.49,1166.91 3560.03,1166.91 3571.14,1178.02 C110_A1.1@3589.84,1178.02
TX/GPIO1_A2: C110_A2.1 R145_A2.1 U1_A2.52 | length 2924.6
  Top Layer w7: R145_A2.1@4448.56,1319.42 4453.52,1314.45 4531.71,1392.63 4552.43,1392.63 4557.38,1397.59 4558.23,1397.59 4564.04,1403.39 4568.99,1403.39 4584.06,1418.46 v1(4584.33,1418.46) ; U1_A2.52@5758.23,1218.37 U1_A2.52@5728.89,1218.37 5731.3,1215.97 5763.87,1215.97 5766.33,1213.51 5792.44,1213.51 5796.21,1217.28 v1(5800.28,1217.28)
  Signal Layer 2 w7: v1(4584.33,1418.46) 4581.46,1421.33 4581.46,1438.19 4579.76,1439.89 4579.76,1457.38 4671.72,1549.34 4671.72,1552.3 4741.34,1621.92 4741.34,1900.84 4745.44,1904.94 5909.57,1904.94 5985.91,1828.6 5985.91,1402.92 v1(5800.28,1217.28)
  Bottom Layer w7: v1@4584.33,1414.76 v1(4584.33,1418.46) ; v1(5800.28,1217.28) 5823.39,1194.16 5823.39,1180.02 5836.5,1166.91 5855.04,1166.91 5866.15,1178.02 C110_A2.1@5884.86,1178.02
TX/GPIO1_A3: C110_A3.1 R145_A3.1 U1_A3.52 | length 2923
  Top Layer w7: R145_A3.1@6785.15,1322.63 6790.12,1317.66 6868.3,1395.84 6889.02,1395.84 6893.98,1400.79 6894.83,1400.79 6900.64,1406.6 6905.59,1406.6 6920.65,1421.67 v1(6922.42,1421.67) ; U1_A3.52@8094.83,1221.58 U1_A3.52@8065.49,1221.58 8067.9,1219.18 8100.47,1219.18 8102.93,1216.72 8129.04,1216.72 8132.81,1220.49 v1(8136.87,1220.49)
  Signal Layer 2 w7: v1(6922.42,1421.67) 6919.55,1424.54 6919.55,1439.9 6916.35,1443.1 6916.35,1460.59 7008.31,1552.55 7008.31,1555.5 7077.94,1625.13 7077.94,1904.05 7082.04,1908.15 8246.17,1908.15 8322.51,1831.81 8322.51,1406.13 v1(8136.87,1220.49)
  Bottom Layer w7: v1(8136.87,1220.49) 8159.99,1197.37 8159.99,1183.23 8173.1,1170.12 8191.64,1170.12 8202.75,1181.23 C110_A3.1@8221.45,1181.23
TX/GPIO1_A4: C110_A4.1 R145_A4.1 U1_A4.52 | length 2923
  Top Layer w7: R145_A4.1@9105.38,1319.42 9110.35,1314.45 9188.53,1392.63 9209.25,1392.63 9214.21,1397.59 9215.06,1397.59 9220.86,1403.39 9225.81,1403.39 9240.88,1418.46 v1(9242.65,1418.46) ; U1_A4.52@10415.06,1218.37 U1_A4.52@10385.72,1218.37 10388.12,1215.97 10420.7,1215.97 10423.16,1213.51 10449.27,1213.51 10453.04,1217.28 v1(10457.1,1217.28)
  Signal Layer 2 w7: v1(9242.65,1418.46) 9239.78,1421.33 9239.78,1436.69 9236.58,1439.89 9236.58,1457.38 9328.54,1549.34 9328.54,1552.3 9398.17,1621.92 9398.17,1900.84 9402.27,1904.94 10566.4,1904.94 10642.74,1828.6 10642.74,1402.92 v1(10457.1,1217.28)
  Bottom Layer w7: v1(10457.1,1217.28) 10480.22,1194.16 10480.22,1180.02 10493.33,1166.91 10511.87,1166.91 10522.98,1178.02 C110_A4.1@10541.68,1178.02
VC0_A1: C106_A1.2 C107_A1.1 R139_A1.2 U1_A1.40 | length 3733.8
  Top Layer w8: R139_A1.2@2801.57,3384.01 2801.57,3380.08 2793.76,3372.26 2773.05,3372.26 2749.31,3348.52 2704.67,3348.52 2688.97,3332.82 2644.33,3332.82 2549.73,3238.21 2352.8,3238.21 2327.25,3212.66 2327.25,3015.74 2327.24,1962.95 2353,1937.19 2484.87,1937.19 2566.67,1937.19 2591.76,1912.1 2591.76,1869.72 2601.61,1859.87 2601.61,1730.44 2583.51,1712.34 2583.51,1185.27 2921.15,847.63 3012.01,847.63 3052.93,888.56 3070.87,888.56 3072.81,888.56 C107_A1.1@3072.86,888.51 ; C107_A1.1@3074.83,886.54 3084.61,896.32 3084.61,904.58 3099.16,919.12 C106_A1.2@3099.16,942.93 3103.09,942.93 3110.9,950.75 3118.41,950.75 3168.93,1001.27 3186.79,1001.27 3190.13,1004.61 3190.84,1004.61 3200.91,1014.67 3200.91,1081.26 U1_A1.40@3199.62,1082.55
VC0_A2: C106_A2.2 C107_A2.1 R139_A2.2 U1_A2.40 | length 3746.6
  Top Layer w8: R139_A2.2@5096.59,3384.01 5096.59,3380.08 5088.78,3372.26 5068.07,3372.26 5044.32,3348.52 4994.98,3348.52 4884.68,3238.21 4647.82,3238.21 4611.85,3202.24 4611.85,1973.35 4648.02,1937.19 4861.69,1937.19 4886.78,1912.1 4886.78,1884.87 4901.57,1870.08 4901.57,1730.36 4878.53,1707.32 4878.53,1185.27 5216.17,847.63 5307.02,847.63 5347.95,888.56 5365.88,888.56 5367.83,888.56 C107_A2.1@5367.88,888.51 ; C107_A2.1@5369.85,886.54 5379.63,896.32 5379.63,904.58 5394.17,919.12 C106_A2.2@5394.17,942.93 5398.11,942.93 5405.92,950.75 5413.42,950.75 5463.95,1001.27 5481.81,1001.27 5485.15,1004.61 5485.86,1004.61 5495.92,1014.67 5495.92,1081.26 U1_A2.40@5494.64,1082.55
VC0_A3: C106_A3.2 C107_A3.1 R139_A3.2 U1_A3.40 | length 3739.1
  Top Layer w8: R139_A3.2@7433.19,3387.22 7433.19,3383.28 7425.37,3375.47 7404.67,3375.47 7380.92,3351.73 7291.64,3351.73 7272.01,3332.09 7074.57,3332.09 6948.45,3205.97 6948.45,1976.49 6980.81,1944.13 6980.88,1944.13 6984.61,1940.4 7198.29,1940.4 7223.38,1915.31 7223.38,1864.08 7227.59,1859.87 7227.59,1722.99 7215.12,1710.52 7215.12,1188.48 7552.76,850.84 7643.62,850.84 7684.55,891.77 7702.48,891.77 7704.42,891.77 C107_A3.1@7704.48,891.71 ; C107_A3.1@7705.73,889.04 7716.22,899.53 7716.22,907.79 7730.77,922.33 C106_A3.2@7730.77,946.14 7734.71,946.14 7742.52,953.95 7750.02,953.95 7800.55,1004.48 7818.41,1004.48 7821.74,1007.82 7822.46,1007.82 7832.52,1017.88 7832.52,1084.47 U1_A3.40@7831.24,1085.75
VC0_A4: C106_A4.2 C107_A4.1 R139_A4.2 U1_A4.40 | length 3741.6
  Top Layer w8: R139_A4.2@9753.42,3384.01 9753.42,3380.08 9745.6,3372.26 9724.9,3372.26 9701.15,3348.52 9611.87,3348.52 9592.24,3328.88 9394.8,3328.88 9274.76,3208.84 9274.76,1965.84 9299.68,1940.92 9301.11,1940.92 9304.84,1937.19 9518.52,1937.19 9548.6,1907.11 9548.6,1878.57 9557.09,1870.08 9557.09,1729.05 9535.35,1707.32 9535.35,1185.27 9872.99,847.63 9963.85,847.63 10004.78,888.56 10022.71,888.56 10024.65,888.56 C107_A4.1@10024.71,888.51 ; C107_A4.1@10026.67,886.54 10036.45,896.32 10036.45,904.58 10051,919.12 C106_A4.2@10051,942.93 10054.94,942.93 10062.75,950.75 10070.25,950.75 10120.78,1001.27 10138.64,1001.27 10141.97,1004.61 10142.69,1004.61 10152.75,1014.67 10152.75,1081.26 U1_A4.40@10151.47,1082.55
VC1_A1: C105_A1.2 C106_A1.1 R138_A1.2 U1_A1.38 | length 3696.2
  Top Layer w8: R138_A1.2@2858.44,3384.01 2834.63,3384.01 2825.26,3374.64 2825.26,3363.35 2794.55,3332.64 2723.55,3332.64 2707.85,3316.94 2650.91,3316.94 2556.3,3222.34 2359.38,3222.34 2343.12,3206.08 2343.12,3009.16 2343.12,1969.52 2359.57,1953.06 2491.44,1953.06 2573.25,1953.06 2607.64,1918.68 2607.64,1876.29 2617.49,1866.44 2617.49,1723.87 2599.39,1705.76 2599.39,1191.85 2927.73,863.5 2980.64,863.5 2987.59,870.46 2987.59,871.51 3001.94,885.85 3009.79,885.83 3040.16,916.2 3040.16,935.12 3047.98,942.93 C106_A1.1@3051.91,942.93 3055.85,942.93 3071.53,958.62 3071.53,959.66 3078.49,966.62 3109.49,966.62 3155.15,1012.28 3155.15,1037.02 3159.15,1041.02 3159.15,1081.44 U1_A1.38@3160.25,1082.55 ; C105_A1.2@3007.21,887.19 C105_A1.2@3008.58,885.83
VC1_A2: C105_A2.2 C106_A2.1 R138_A2.2 U1_A2.38 | length 3708.9
  Top Layer w8: R138_A2.2@5153.46,3384.01 5129.65,3384.01 5120.27,3374.64 5120.27,3363.35 5089.57,3332.64 5001.56,3332.64 4891.25,3222.34 4654.39,3222.34 4627.73,3195.67 4627.73,1979.93 4654.59,1953.06 4868.27,1953.06 4902.65,1918.68 4902.65,1891.45 4917.45,1876.65 4917.45,1723.79 4910.79,1717.13 4894.4,1700.74 4894.4,1191.85 5222.74,863.5 5275.65,863.5 5282.61,870.46 5282.61,871.51 C105_A2.2@5296.96,885.85 ; C105_A2.2@5296.98,885.83 5304.8,885.83 5335.18,916.2 5335.18,935.12 5342.99,942.93 C106_A2.1@5346.93,942.93 5350.87,942.93 5366.55,958.62 5366.55,959.66 5373.51,966.62 5404.51,966.62 5450.17,1012.28 5450.17,1037.02 5454.17,1041.02 5454.17,1081.44 U1_A2.38@5455.27,1082.55 ; C105_A2.2@5302.23,887.19 C105_A2.2@5303.59,885.83
VC1_A3: C105_A3.2 C106_A3.1 R138_A3.2 U1_A3.38 | length 3697.8
  Top Layer w8: R138_A3.2@7490.05,3387.22 7466.24,3387.22 7456.87,3377.85 7456.87,3366.55 7426.17,3335.85 7298.22,3335.85 7278.58,3316.22 7081.15,3316.22 6964.32,3199.39 6964.32,1983.06 6987.39,1960 6987.46,1960 6991.19,1956.27 7204.86,1956.27 7239.25,1921.88 7239.25,1870.65 7243.46,1866.44 7243.46,1716.41 7231,1703.95 7231,1195.05 7559.34,866.71 7612.25,866.71 7619.2,873.67 7619.2,874.71 7634.89,890.4 C105_A3.2@7638.83,890.4 ; C105_A3.2@7640.19,889.04 7641.4,889.04 7671.78,919.41 7671.78,938.33 7679.59,946.14 C106_A3.1@7683.53,946.14 7687.46,946.14 7703.15,961.83 7703.15,962.87 7710.1,969.83 7741.11,969.83 7786.76,1015.49 7786.76,1040.23 7790.76,1044.23 7790.76,1084.65 U1_A3.38@7791.87,1085.75
VC1_A4: C105_A4.2 C106_A4.1 R138_A4.2 U1_A4.38 | length 3703.9
  Top Layer w8: R138_A4.2@9810.28,3384.01 9786.47,3384.01 9777.1,3374.64 9777.1,3363.35 9746.4,3332.64 9618.45,3332.64 9598.81,3313.01 9401.38,3313.01 9290.63,3202.26 9290.63,1972.41 9306.25,1956.79 9307.69,1956.79 9311.42,1953.06 9525.09,1953.06 9564.47,1913.68 9564.47,1885.14 9572.96,1876.65 9572.96,1722.47 9566.29,1715.8 9551.23,1700.74 9551.23,1191.85 9879.57,863.51 9932.48,863.51 9939.43,870.46 9939.43,871.51 9953.78,885.85 9961.63,885.83 9992.01,916.2 9992.01,935.12 9999.82,942.93 C106_A4.1@10003.76,942.93 10007.69,942.93 10023.38,958.62 10023.38,959.66 10030.33,966.62 10061.34,966.62 10106.99,1012.28 10106.99,1037.02 10110.99,1041.02 10110.99,1081.44 U1_A4.38@10112.1,1082.55 ; C105_A4.2@9959.06,887.19 C105_A4.2@9960.42,885.83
